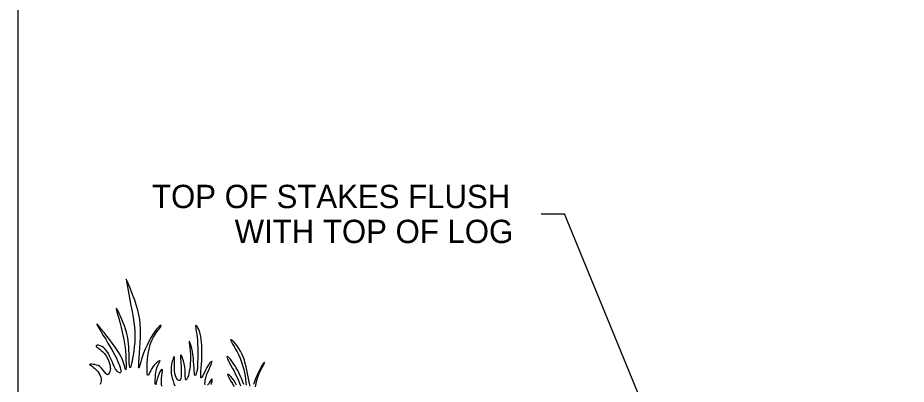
# Model space of a CAD drawing. Extents: x 99862 to 103680, y 99470 to 102076.
# Drawn here: x 99862 to 100472, y 100493 to 100744 of the extents above; entities that cross this region are included whole.
import ezdxf

# ---------------------------------------------------------------- set-up
doc = ezdxf.new("R2010")
doc.units = 0
for name, color, linetype in [('Level 1', 7, 'Continuous'), ('Level 15', 7, 'Continuous'), ('Level 20', 7, 'Continuous'), ('Level 6', 7, 'Continuous')]:
    doc.layers.add(name, color=color, linetype=linetype)

msp = doc.modelspace()

# ---------------------------------------------------------------- linework, layer by layer
at = {"layer": 'Level 1'}
msp.add_lwpolyline([(99862, 99999.5), (103151, 99999.5), (103151, 102075.5), (99862, 102075.5)], close=True, dxfattribs=at)
at = {"layer": 'Level 15'}
for p in [(100221.57, 100609.55), (100299.34, 100459.21)]:
    msp.add_line(p, (100237.57, 100609.55), dxfattribs=at)
at = {"layer": 'Level 6'}
for points in [[(99956.44, 100492.63), (99956.42, 100493.84), (99956.44, 100495.4), (99956.52, 100497.19), (99956.69, 100499.1), (99956.94, 100500.99), (99957.29, 100502.76), (99957.63, 100503.98), (99958.02, 100505.05), (99958.42, 100505.98), (99958.82, 100506.77), (99959.18, 100507.42), (99959.47, 100507.94), (99959.68, 100508.33), (99959.78, 100508.6), (99959.44, 100508.73), (99958.93, 100508.53), (99958.24, 100508.13), (99957.43, 100507.53), (99956.54, 100506.73), (99955.64, 100505.73), (99954.75, 100504.52), (99954.04, 100503.32), (99953.39, 100502.07), (99952.8, 100500.88), (99952.28, 100499.87), (99951.83, 100499.13), (99951.46, 100498.78), (99951.17, 100498.92), (99950.96, 100499.67), (99950.82, 100501.35), (99950.81, 100503.75), (99950.93, 100506.7), (99951.2, 100509.98), (99951.64, 100513.41), (99952.25, 100516.79), (99953.04, 100519.91), (99954.03, 100522.63), (99955.14, 100524.94), (99956.31, 100526.88), (99957.46, 100528.49), (99958.52, 100529.8), (99959.41, 100530.86), (99960.06, 100531.7), (99960.37, 100532.23), (99960.49, 100532.63), (99960.45, 100532.89), (99960.25, 100532.99), (99959.91, 100532.9), (99959.43, 100532.63), (99958.83, 100532.14), (99958.12, 100531.42), (99957.3, 100530.45), (99956.12, 100528.83), (99954.84, 100526.84), (99953.49, 100524.56), (99952.14, 100522.05), (99950.82, 100519.39), (99949.58, 100516.66), (99948.46, 100513.91), (99947.71, 100511.82), (99947.06, 100509.83), (99946.5, 100508.01), (99946.04, 100506.41), (99945.67, 100505.1), (99945.39, 100504.15), (99945.19, 100503.61), (99945.07, 100503.55), (99945.03, 100504.03), (99945.08, 100505.48), (99945.23, 100507.75), (99945.43, 100510.65), (99945.67, 100513.98), (99945.92, 100517.56), (99946.14, 100521.22), (99946.3, 100524.75), (99946.38, 100528.02), (99946.35, 100531.1), (99946.16, 100534.08), (99945.8, 100537.07), (99945.24, 100540.19), (99944.43, 100543.53), (99943.35, 100547.2), (99942.32, 100550.32), (99941.16, 100553.56), (99939.95, 100556.78), (99938.74, 100559.82), (99937.6, 100562.55), (99936.58, 100564.81), (99939.72, 100546.75), (99940.6, 100542.56), (99941.33, 100538.49), (99941.98, 100533.64), (99942.32, 100529.21), (99942.42, 100525.19), (99942.31, 100521.54), (99942.05, 100518.24), (99941.69, 100515.25), (99941.28, 100512.57), (99940.92, 100510.45), (99940.56, 100508.57), (99940.21, 100506.97), (99939.89, 100505.69), (99939.59, 100504.76), (99939.32, 100504.22), (99939.08, 100504.11), (99938.9, 100504.46), (99938.74, 100505.46), (99938.64, 100506.98), (99938.57, 100508.92), (99938.51, 100511.14), (99938.46, 100513.52), (99938.39, 100515.94), (99938.29, 100518.28), (99938.14, 100520.44), (99937.93, 100522.46), (99937.63, 100524.4), (99937.23, 100526.33), (99936.71, 100528.31), (99936.06, 100530.4), (99935.25, 100532.69), (99934.41, 100534.85), (99933.5, 100537.08), (99932.57, 100539.25), (99931.68, 100541.21), (99930.89, 100542.86), (99930.25, 100544.05), (99929.83, 100544.65), (99929.67, 100544.55), (99929.86, 100543.45), (99930.39, 100541.43), (99931.16, 100538.65), (99932.07, 100535.28), (99933.05, 100531.49), (99934, 100527.46), (99934.83, 100523.35), (99935.46, 100519.33), (99935.9, 100515.5), (99936.18, 100511.97), (99936.34, 100508.86), (99936.39, 100506.25), (99936.37, 100504.27), (99936.3, 100503), (99936.24, 100502.59), (99936.15, 100502.55), (99936.03, 100502.84), (99935.87, 100503.43), (99935.64, 100504.27), (99935.35, 100505.34), (99934.97, 100506.59), (99934.49, 100507.98), (99933.91, 100509.49), (99933.2, 100511.07), (99932.27, 100512.87), (99931.17, 100514.74), (99929.91, 100516.68), (99928.49, 100518.71), (99926.92, 100520.85), (99925.2, 100523.1), (99923.33, 100525.5), (99921.32, 100528.05), (99919.16, 100530.76), (99919.04, 100530.91), (99918.92, 100531.06), (99918.8, 100531.21), (99917.16, 100533.2), (99916.37, 100533.99), (99916.31, 100533.75), (99916.85, 100532.67), (99917.86, 100530.91), (99919.2, 100528.68), (99920.76, 100526.14), (99922.39, 100523.47), (99923.98, 100520.86), (99925.81, 100517.74), (99927.37, 100515), (99928.66, 100512.59), (99929.73, 100510.48), (99930.6, 100508.63), (99931.3, 100507.01), (99931.84, 100505.59), (99932.32, 100504.15), (99932.64, 100502.92), (99932.79, 100501.93), (99932.79, 100501.18), (99932.64, 100500.67), (99932.33, 100500.4), (99931.78, 100500.42), (99931.05, 100500.84), (99930.19, 100501.69), (99929.24, 100503), (99928.23, 100504.81), (99927.5, 100506.4), (99926.75, 100508.17), (99925.97, 100510.05), (99925.13, 100511.93), (99924.22, 100513.73), (99923.22, 100515.37), (99922.13, 100516.76), (99920.93, 100517.83), (99919.7, 100518.6), (99918.51, 100519.1), (99917.44, 100519.35), (99916.58, 100519.38), (99915.99, 100519.24), (99915.76, 100518.94), (99915.95, 100518.52), (99916.49, 100517.99), (99917.3, 100517.35), (99918.29, 100516.6), (99919.38, 100515.75), (99920.48, 100514.82), (99921.51, 100513.79), (99922.7, 100512.23), (99923.63, 100510.6), (99924.32, 100508.98), (99924.83, 100507.46), (99925.19, 100506.12), (99925.44, 100505.03), (99925.58, 100504.13), (99925.62, 100503.34), (99925.55, 100502.6), (99925.37, 100501.82), (99925.09, 100500.96), (99924.71, 100500.13), (99924.24, 100499.47), (99923.69, 100499.14), (99923.08, 100499.27), (99922.4, 100499.94), (99921.62, 100501.03), (99920.71, 100502.33), (99919.62, 100503.64), (99918.32, 100504.77), (99917.25, 100505.38), (99916.11, 100505.81), (99914.97, 100506.1), (99913.89, 100506.26), (99912.92, 100506.33), (99912.13, 100506.32), (99911.59, 100506.26), (99911.37, 100506.19), (99911.31, 100506.1), (99911.4, 100505.98), (99911.62, 100505.83), (99911.94, 100505.64), (99912.35, 100505.4), (99912.83, 100505.12), (99913.36, 100504.79), (99913.91, 100504.4), (99914.94, 100503.54), (99915.94, 100502.54), (99916.89, 100501.43), (99917.72, 100500.27), (99918.4, 100499.12), (99918.88, 100498.02), (99919.18, 100496.96), (99919.31, 100495.96), (99919.28, 100495), (99919.13, 100494.08), (99918.86, 100493.21), (99918.52, 100492.4)], [(99990.63, 100492.2), (99990.58, 100493.11), (99990.65, 100494.23), (99990.85, 100495.53), (99991.19, 100496.97), (99991.76, 100498.74), (99992.45, 100500.57), (99993.21, 100502.38), (99993.95, 100504.08), (99994.61, 100505.61), (99995.12, 100506.87), (99995.42, 100507.78), (99995.47, 100508.2), (99995.36, 100508.38), (99995.11, 100508.34), (99994.76, 100508.08), (99994.31, 100507.63), (99993.78, 100507.01), (99993.2, 100506.22), (99992.59, 100505.28), (99991.97, 100504.21), (99991.17, 100502.7), (99990.41, 100501.12), (99989.7, 100499.63), (99989.07, 100498.34), (99988.54, 100497.4), (99988.12, 100496.94), (99987.85, 100497.09), (99987.72, 100497.94), (99987.73, 100499.41), (99987.83, 100501.37), (99987.99, 100503.71), (99988.17, 100506.3), (99988.35, 100509.02), (99988.48, 100511.74), (99988.55, 100514.37), (99988.54, 100516.87), (99988.45, 100519.24), (99988.28, 100521.47), (99988.03, 100523.55), (99987.71, 100525.48), (99987.3, 100527.25), (99986.82, 100528.85), (99986.3, 100530.24), (99985.76, 100531.4), (99985.25, 100532.29), (99984.8, 100532.87), (99984.45, 100533.11), (99984.24, 100532.99), (99984.18, 100532.46), (99984.25, 100531.56), (99984.42, 100530.32), (99984.66, 100528.76), (99984.92, 100526.93), (99985.18, 100524.85), (99985.39, 100522.56), (99985.53, 100520.09), (99985.62, 100517.53), (99985.65, 100514.96), (99985.64, 100512.47), (99985.6, 100510.15), (99985.55, 100508.09), (99985.51, 100506.38), (99985.45, 100504.64), (99985.4, 100503.52), (99985.33, 100502.77), (99985.21, 100502.16), (99985.01, 100501.45), (99984.85, 100500.88), (99984.66, 100500.24), (99984.45, 100499.62), (99984.23, 100499.08), (99984.02, 100498.7), (99983.81, 100498.54), (99983.62, 100498.67), (99983.46, 100499.18), (99983.32, 100500.26), (99983.2, 100501.81), (99983.1, 100503.73), (99982.98, 100505.91), (99982.83, 100508.24), (99982.62, 100510.63), (99982.34, 100512.97), (99981.97, 100515.16), (99981.54, 100517.14), (99981.09, 100518.87), (99980.65, 100520.29), (99980.25, 100521.35), (99979.93, 100522.01), (99979.73, 100522.2), (99979.68, 100521.81), (99979.77, 100520.83), (99979.96, 100519.36), (99980.2, 100517.52), (99980.42, 100515.41), (99980.59, 100513.12), (99980.64, 100511.11), (99980.62, 100509.08), (99980.52, 100507.08), (99980.35, 100505.14), (99980.13, 100503.29), (99979.86, 100501.58), (99979.55, 100500.03), (99979.2, 100498.68), (99978.83, 100497.56), (99978.46, 100496.67), (99978.1, 100496.05), (99977.78, 100495.71), (99977.5, 100495.67), (99977.3, 100495.94), (99977.14, 100496.87), (99977.07, 100498.32), (99977.02, 100500.17), (99976.92, 100502.28), (99976.68, 100504.51), (99976.27, 100506.73), (99975.74, 100508.8), (99975.16, 100510.56), (99974.6, 100511.87), (99974.16, 100512.59), (99973.95, 100512.67), (99973.82, 100512.41), (99973.77, 100511.82), (99973.77, 100510.93), (99973.82, 100509.78), (99973.91, 100508.39), (99974.02, 100506.79), (99974.15, 100505.02), (99974.26, 100503.16), (99974.34, 100501.29), (99974.35, 100499.52), (99974.28, 100497.94), (99974.1, 100496.63), (99973.78, 100495.69), (99973.31, 100495.19), (99972.72, 100495.12), (99972.08, 100495.44), (99971.43, 100496.12), (99970.81, 100497.14), (99970.27, 100498.45), (99969.88, 100500.02), (99969.65, 100501.8), (99969.56, 100503.7), (99969.57, 100505.61), (99969.63, 100507.42), (99969.7, 100509.01), (99969.73, 100510.28), (99969.68, 100511.11), (99969.54, 100511.41), (99969.32, 100511.34), (99969.05, 100510.97), (99968.75, 100510.33), (99968.43, 100509.47), (99968.12, 100508.47), (99967.84, 100507.35), (99967.61, 100506.18), (99967.38, 100504.3), (99967.32, 100502.42), (99967.43, 100500.53), (99967.7, 100498.66), (99968.12, 100496.79), (99968.67, 100494.94), (99969.27, 100493.15), (99969.82, 100491.47)], [(100021.58, 100491.25), (100021.23, 100493.19), (100020.82, 100495.35), (100020.39, 100497.64), (100019.92, 100499.99), (100019.44, 100502.34), (100018.91, 100504.66), (100018.32, 100506.95), (100017.66, 100509.18), (100016.9, 100511.34), (100016.03, 100513.42), (100015.03, 100515.39), (100013.89, 100517.24), (100012.68, 100518.94), (100011.48, 100520.41), (100010.36, 100521.63), (100009.4, 100522.55), (100008.68, 100523.1), (100008.27, 100523.26), (100008.23, 100522.97), (100008.52, 100522.3), (100009.07, 100521.28), (100009.83, 100519.98), (100010.72, 100518.45), (100011.68, 100516.74), (100012.66, 100514.92), (100013.58, 100513.03), (100014.45, 100511.08), (100015.25, 100509.07), (100015.99, 100507), (100016.65, 100504.87), (100017.24, 100502.69), (100017.75, 100500.46), (100018.18, 100498.19), (100018.52, 100495.97), (100018.77, 100493.9), (100018.93, 100492.07)], [(100017.26, 100492.34), (100016.62, 100494.08), (100015.87, 100495.99), (100015.03, 100497.99), (100014.1, 100499.99), (100013.1, 100501.94), (100012.06, 100503.82), (100011.01, 100505.57), (100009.98, 100507.17), (100009, 100508.57), (100008.1, 100509.75), (100007.41, 100510.56), (100006.81, 100511.15), (100006.32, 100511.53), (100005.96, 100511.68), (100005.75, 100511.6), (100005.7, 100511.29), (100005.82, 100510.72), (100006.13, 100509.91), (100006.72, 100508.68), (100007.53, 100507.16), (100008.48, 100505.42), (100009.53, 100503.51), (100010.62, 100501.49), (100011.68, 100499.41), (100012.67, 100497.33), (100013.54, 100495.29), (100014.28, 100493.33), (100014.91, 100491.46)], [(100025.34, 100490.8), (100025.74, 100493.08), (100026.26, 100495.29), (100026.9, 100497.37), (100027.62, 100499.3), (100028.39, 100501.06), (100029.16, 100502.63), (100029.88, 100504.02), (100030.51, 100505.2), (100031.01, 100506.16), (100031.27, 100506.75), (100031.43, 100507.2), (100031.48, 100507.48), (100031.28, 100507.55), (100031.03, 100507.31), (100030.69, 100506.87), (100030.26, 100506.23), (100029.74, 100505.38), (100028.96, 100503.97), (100028.08, 100502.28), (100027.15, 100500.38), (100026.22, 100498.37), (100025.33, 100496.32), (100024.54, 100494.31), (100023.88, 100492.43)], [(99960.88, 100491.27), (99960.65, 100492.97), (99960.65, 100494.82), (99960.78, 100496.71), (99960.99, 100498.53), (99961.21, 100500.15), (99961.36, 100501.47), (99961.37, 100502.36), (99961.23, 100502.73), (99960.96, 100502.74), (99960.6, 100502.43), (99960.15, 100501.85), (99959.67, 100501.05), (99959.17, 100500.06), (99958.68, 100498.95), (99958.23, 100497.75), (99957.88, 100496.65), (99957.58, 100495.56), (99957.32, 100494.53), (99957.11, 100493.59), (99956.93, 100492.8), (99956.79, 100492.18)], [(99994.67, 100492.33), (99994.83, 100492.76), (99994.88, 100492.87), (99994.96, 100493.06), (99995.06, 100493.3), (99995.13, 100493.51), (99995.18, 100493.66), (99995.22, 100493.8), (99995.27, 100493.95), (99995.31, 100494.06), (99995.35, 100494.22), (99995.39, 100494.39), (99995.43, 100494.61), (99995.46, 100494.77), (99995.49, 100494.91), (99995.53, 100495.2), (99995.55, 100495.63), (99995.53, 100496.03), (99995.37, 100496.32), (99995.06, 100496.1), (99994.63, 100495.51), (99994.12, 100494.67), (99993.56, 100493.7), (99992.98, 100492.73), (99992.41, 100491.89)], [(100012.19, 100492.04), (100011.26, 100493.77), (100010.32, 100495.31), (100009.27, 100496.8), (100008.29, 100497.94), (100007.44, 100498.74), (100006.76, 100499.22), (100006.3, 100499.37), (100006.1, 100499.21), (100006.24, 100498.63), (100006.73, 100497.67), (100007.49, 100496.39), (100008.42, 100494.82), (100009.44, 100493.04), (100010.46, 100491.08)]]:
    msp.add_lwpolyline(points, dxfattribs=at)

# ---------------------------------------------------------------- texts
at = {"layer": 'Level 20'}
for s, p in [('TOP OF STAKES FLUSH ', (99954.22, 100613.55)), ('WITH TOP OF LOG', (100011.02, 100589.55))]:
    msp.add_text(s, height=16, dxfattribs=at).set_placement(p)

doc.saveas('drawing.dxf')
